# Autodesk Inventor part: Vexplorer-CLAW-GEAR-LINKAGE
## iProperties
Created: 2007-10
Part Number: Vexplorer-CLAW-GEAR-LINKAGE
Document SubType Name: Modeling
Material: ABS Plastic
Density: 1.06 g/cm^3
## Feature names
1. Base1
